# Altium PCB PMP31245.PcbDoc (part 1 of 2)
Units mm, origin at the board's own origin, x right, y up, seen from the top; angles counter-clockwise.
Board outline 106.43 x 50.29 mm, 4 copper layers (Top Layer, GND, Layer 2, Bottom Layer), stack 0.603 mm thick; 132 components, 64 nets, 341 pads, 146 vias.
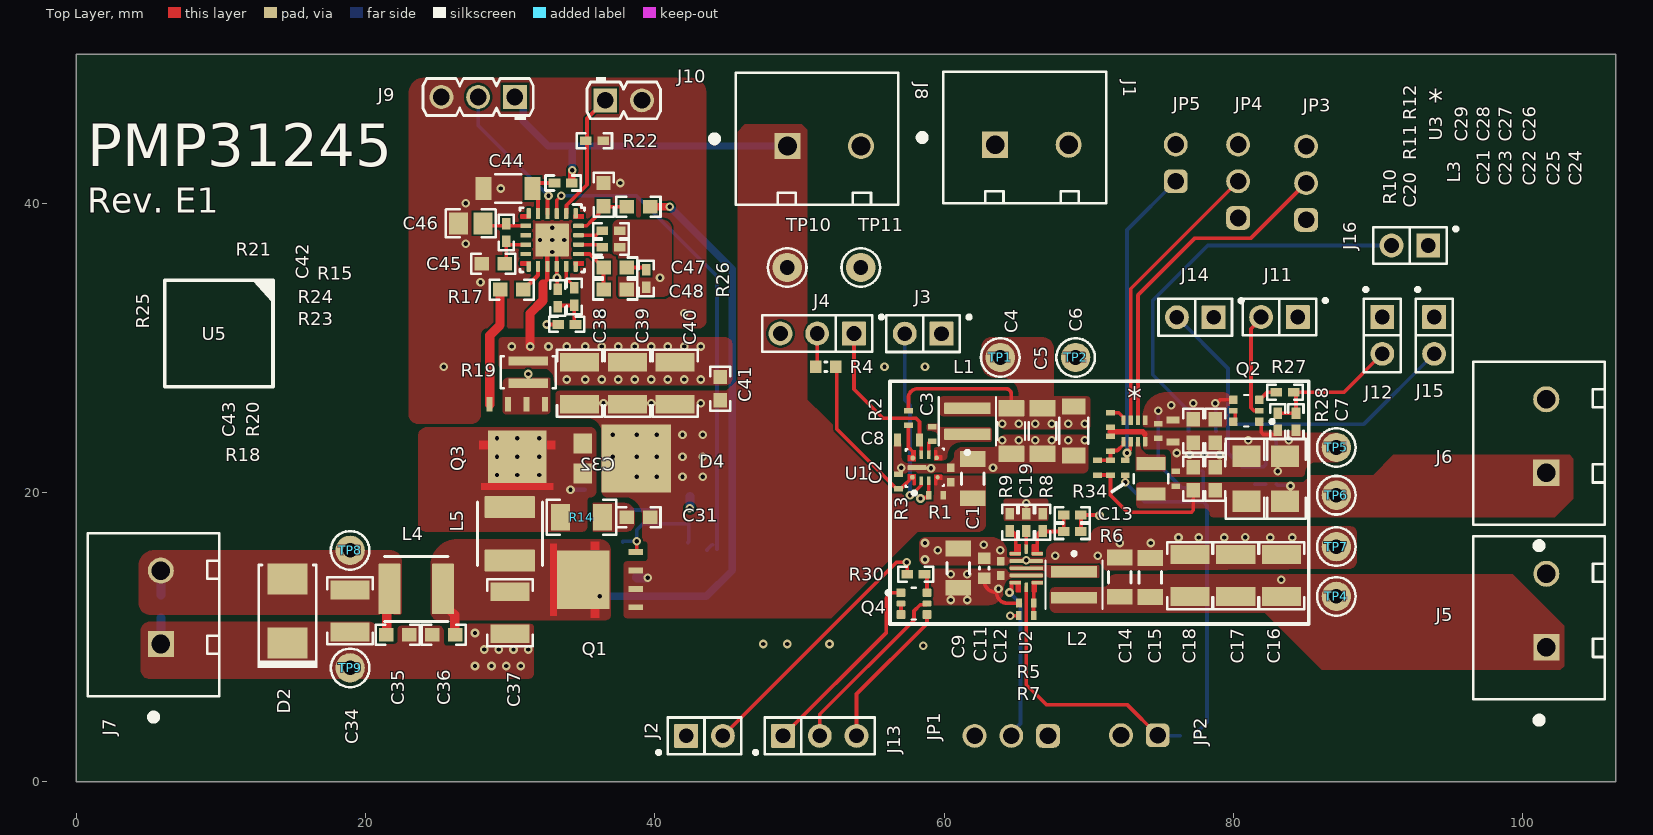
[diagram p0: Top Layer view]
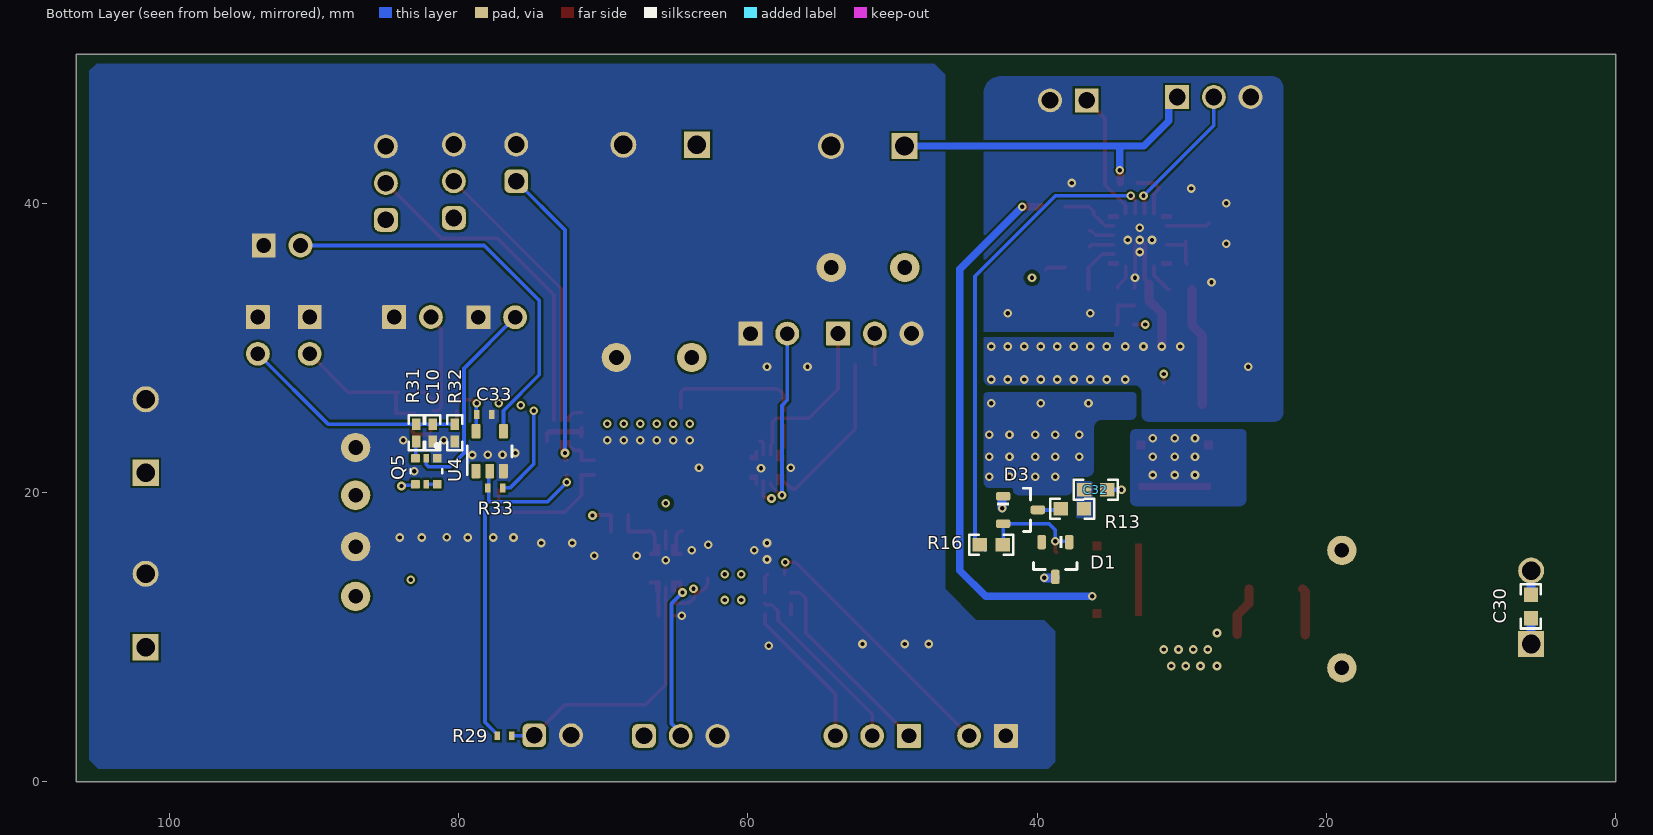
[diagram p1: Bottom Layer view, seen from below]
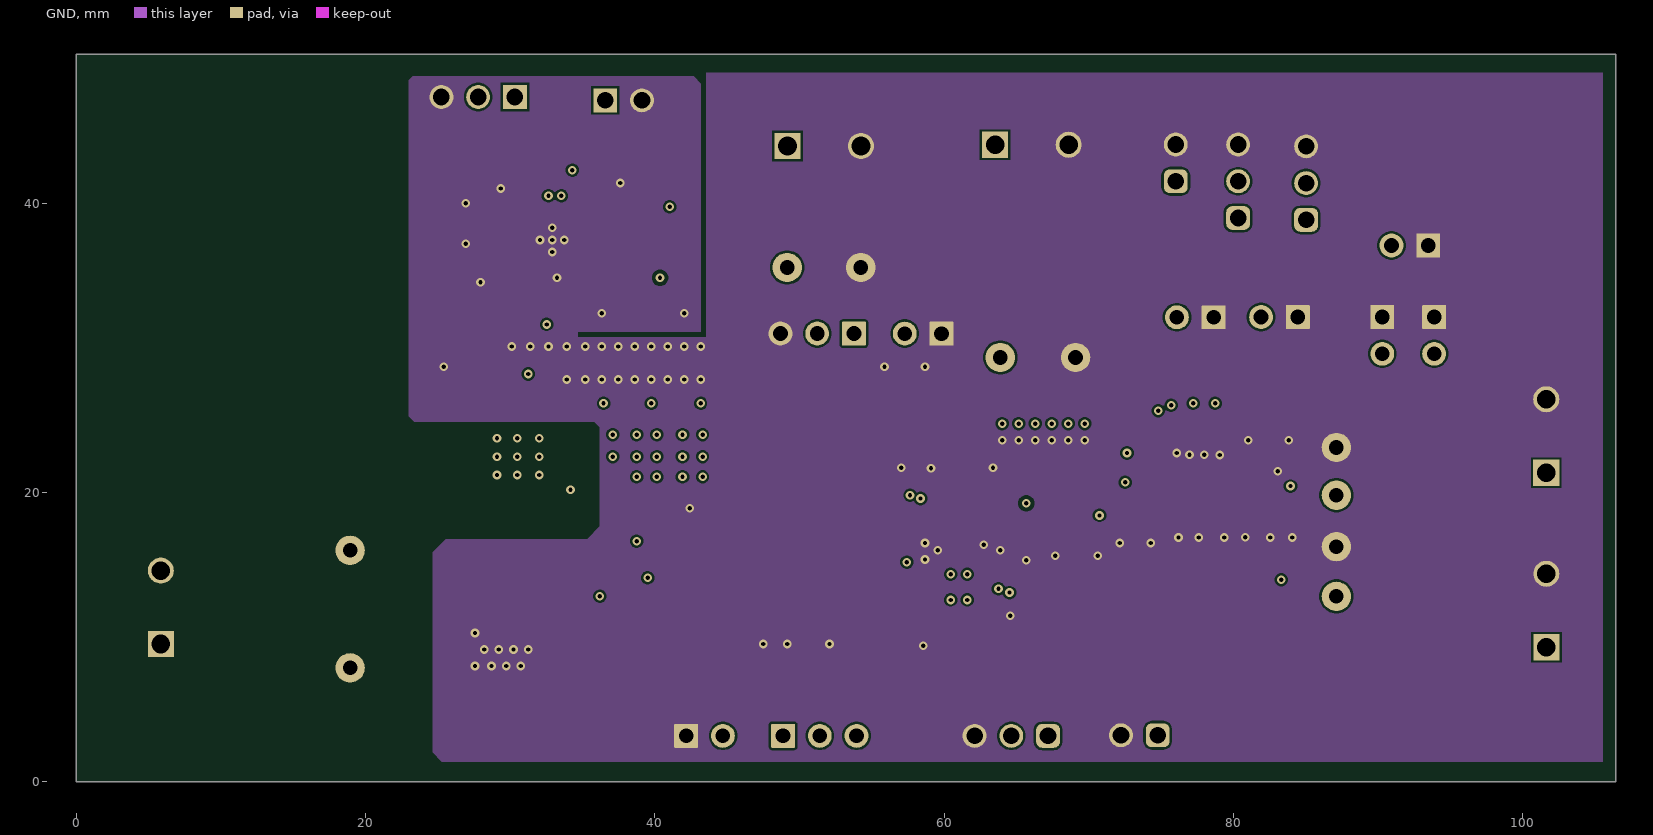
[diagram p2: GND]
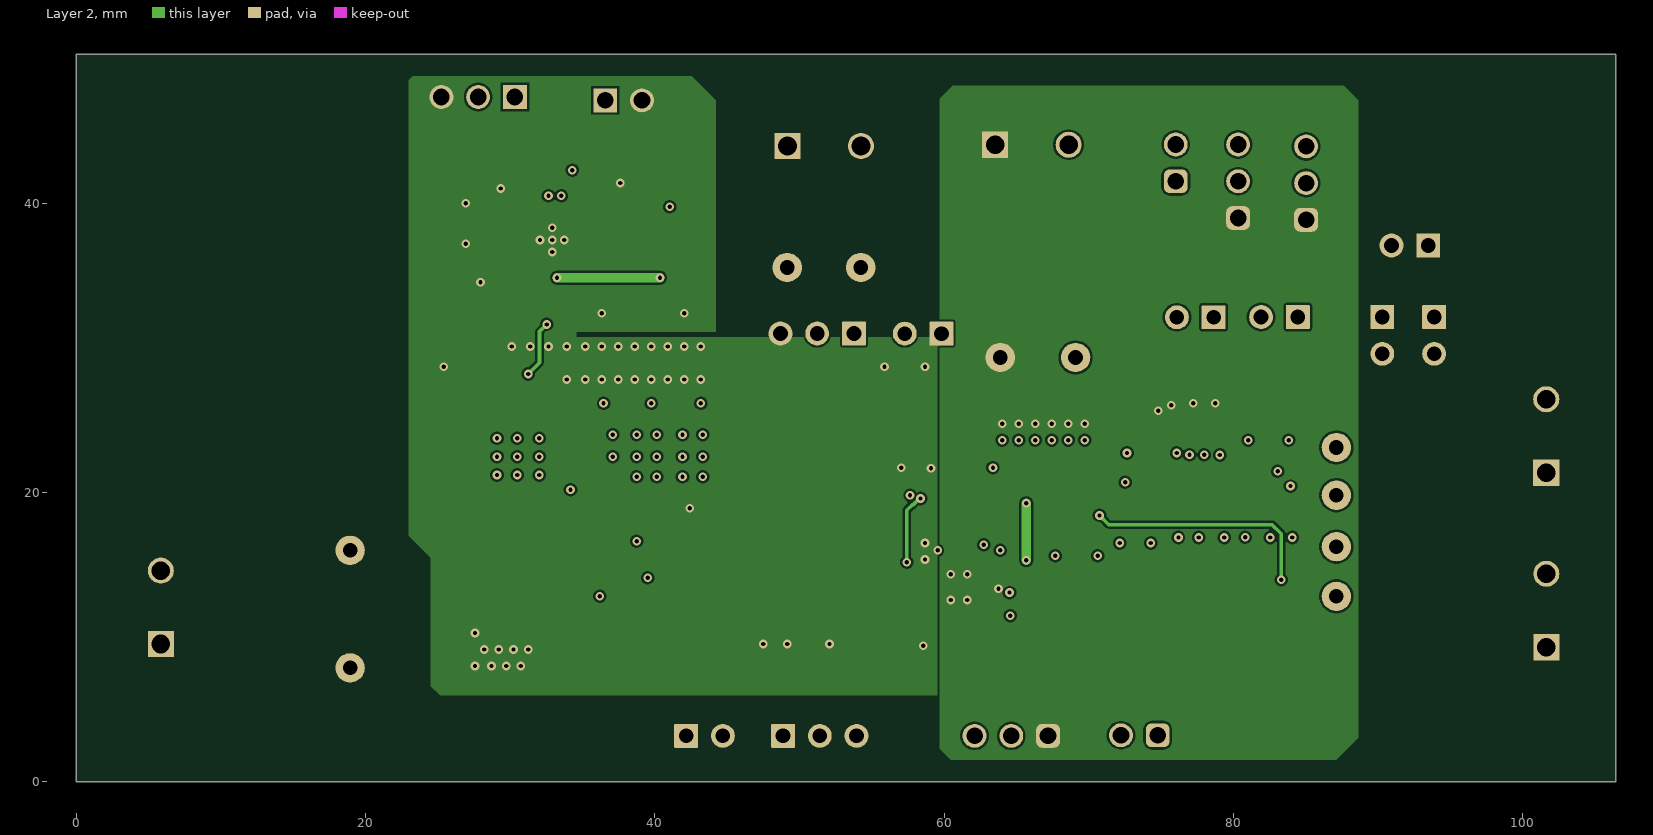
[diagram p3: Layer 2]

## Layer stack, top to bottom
Top Solder: solder mask 0.0102, Solder Resist, Dk 3.5
Top Layer: signal copper 0.0356
Dielectric 2: prepreg 0.0711, PP-006, Dk 4.1
GND: signal copper 0.035
Dielectric 1: dielectric 0.32, FR-4, Dk 4.8
Layer 2: signal copper 0.035
Dielectric 3: prepreg 0.0711, PP-006, Dk 4.1
Bottom Layer: signal copper 0.0356
Bottom Solder: solder mask 0.0102, Solder Resist, Dk 3.5

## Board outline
0,0 0,50.292 106.426,50.292 106.426,0

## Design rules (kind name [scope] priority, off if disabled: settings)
Clearance [All] p1: gap=0.152 ignorepadtopadclearanceinfootprint=FALSE except(0: Arc-Hole Track-Hole SMDPad-Hole THPad-Hole Via-Hole Fill-Hole Poly-Hole Region-Hole Text-Hole)
HoleSize [All] p1: absolutevalues=TRUE maxlimit=2.54 minlimit=0.3 maxpercent=80.000 minpercent=20.000
MinimumAnnularRing [All] p1: minimumring=0.2
PolygonConnect [All] p1: connectstyle=Direct reliefconductorwidth=0.254 reliefentries=4 polygonreliefangle="90 Angle" airgapwidth=0.254
RoutingVias [All] p1: holewidth=0.3 width=0.6 viastyle="Through Hole" minholewidth=0.3 minwidth=0.6 maxholewidth=0.711 maxwidth=1.27
SolderMaskExpansion [All] p1: expansion=0.102 istentingtop=FALSE
Width [All] p1: maxlimit=1.27 minlimit=0.254 preferedwidth=0.254 minimp=50.000000 maximp=50.000000 favimp=50.000000
29 further rules are at their usual default settings.

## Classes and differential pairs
component class PMP31245_Boost: C30 C31 C32 C34 C35 C36 C37 C38 C39 C40 C41 C42 C43 C44 C45 C46 C47 C48 D1 D2 D3 D4 J7 J8 J9 J10 L4 L5 Q1 Q3 R13 R14 R15 R16 R17 R18 R19 R20 R21 R22 R23 R24 R25 R26 TP8 TP9 TP10 TP11 U5
component class PMP31245_Buck: C1 C2 C3 C4 C5 C6 C7 C8 C9 C10 C11 C12 C13 C14 C15 C16 C17 C18 C19 C20 C21 C22 C23 C24 C25 C26 C27 C28 C29 C33 J1 J2 J3 J4 J5 J6 J11 J12 J13 J14 J15 J16 JP1 JP2 JP3 JP4 JP5 L1 L2 L3 Q2 Q4 Q5 R1 R2 R3 R4 R5 R6 R7 R8 R9 R10 R11 R12 R27 R28 R29 R30 R31 R32 R33 R34 TP1 TP2 TP4 TP5 TP6 TP7 U1 U2 U3 U4

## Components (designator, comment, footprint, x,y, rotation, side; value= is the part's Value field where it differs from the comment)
C1 "CIN" 1206_180L 61.976,20.955 r270 top value=4.7uF
C2 "CINHF" 0402L 60.452,21.209 r90 top value=0.1uF
C3 "CB" 0402S 59.178,24.051 r90 top value=0.1uF
C4 "COUT1" FP-GRM31CC81E226KE11L_1206-MFG 64.643,24.257 r90 top value=22µF
C5 "COUT2" FP-GRM31CC81E226KE11L_1206-MFG 66.802,24.257 r90 top value=22µF
C6 "COUT3" 1206_190 68.961,24.257 r90 top value=10uF
C7 "CGA2B2X7R1H222K050BA" 0402 84.328,24.892 r270 top value=2200pF
C8 "CVCC" 0603S 57.531,23.622 r180 top value=1uF
C9 "GCM31CR71A226KE02" 1206_180L 60.985,14.765 r90 top value=22uF
C10 "CGA2B2X7R1H222K050BA" 0402 81.788,24.13 r270 bottom value=2200pF
C11 "GCM188C71A225K" 0603L 62.763,14.765 r90 top value=2.2uF
C12 "GCM155R71H471KA37D" 0402L 63.906,14.757 r90 top value=470pF
C13 "GCM1555C1H220JA16D" 0402 68.859,18.448 r180 top value=22pF
C14 "GCM31CR71A226KE02" 1206_180L 72.136,14.144 r90 top value=22uF
C15 "GCM31CR71A226KE02" 1206_180L 74.261,14.128 r90 top value=22uF
C16 "GRM32ER60J107ME20L" 1210_270 83.337,14.257 r90 top value=100uF
C17 "GRM32ER60J107ME20L" 1210_270 80.162,14.257 r90 top value=100uF
C18 "GRM32ER60J107ME20L" 1210_270 76.987,14.257 r90 top value=100uF
C19 "GCM155R71H472KA37D" 0402 65.684,17.94 r90 top value=4700pF
C20 "GCM1555C1H100JA16D" 0402S 71.501,21.717 r90 top value=10pF
C21 "C0402C104K4RACAUTO" 0402S 76.015,20.952 r90 top value=0.1uF
C22 "GRM188Z71A106MA73D" 0603 78.74,20.955 r90 top value=10uF
C23 "GRM188Z71A106MA73D" 0603 77.216,20.955 r90 top value=10uF
C24 "GCM31CR71A226KE02" 1206_180M 83.566,20.955 r90 top value=22uF
C25 "GCM31CR71A226KE02" 1206_180M 80.899,20.955 r90 top value=22uF
C26 "GRM188Z71A106MA73D" 0603 78.74,24.257 r270 top value=10uF
C27 "GRM188Z71A106MA73D" 0603 77.216,24.257 r270 top value=10uF
C28 "GRM188R71C474KA88D" 0603S 75.819,24.257 r270 top value=0.47uF
C29 "CGA2B2X7R1H471K050BA" 0402S 74.803,24.257 r90 top value=470pF
C30 "GRM188R71H104KA93D" 0603 5.851,12.12 r90 bottom value=0.1uF
C31 "GRM188R71H271KA01D" 0603 38.862,18.288 r180 top value=270pF
C32 "GRM188R72A103KA01D" 0603 35.941,20.193 r180 bottom value=0.01uF
C33 "C0402C104K4RACAUTO" 0402S 78.232,25.4 r180 bottom value=0.1uF
C34 "GRM32ER71H106KA12L" 1210_270 18.923,11.811 r270 top value=10uF
C35 "GRM188R71H104KA93D" 0603 22.225,10.16 r180 top value=0.1uF
C36 "GRM188R71H104KA93D" 0603 25.4,10.16 r0 top value=0.1uF
C37 "GRM32ER71H106KA12L" 1210_270 29.972,11.684 r270 top value=10uF
C38 "GRM32ER71H106KA12L" 1210_270 34.798,27.559 r90 top value=10uF
C39 "GRM32ER71H106KA12L" 1210_270 38.1,27.559 r90 top value=10uF
C40 "GRM32ER71H106KA12L" 1210_270 41.402,27.559 r90 top value=10uF
C41 "GRM188R71H104KA93D" 0603 44.513,27.187 r90 top value=0.1uF
C42 "GRM188R71H104KA93D" 0603 36.449,40.602 r270 top value=0.1uF
C43 "CGA2B2X7R1H222K050BA" 0402 33.277,33.445 r270 top value=2200pF
C44 "GRM31CR71H225KA88L" 1206_180 29.845,41.021 r180 top value=2.2uF
C45 "GRM188R71H104KA93D" 0603 28.829,35.814 r180 top value=0.1uF
C46 "GRM21BR71C475KA73L" 0805 27.266,38.608 r0 top value=4.7uF
C47 "GRM188R71E474KA12D" 0603 37.249,35.56 r0 top value=0.47uF
C48 "GRM188R71H683KA93D" 0603 37.249,34.036 r0 top value=0.068uF
D1 "BZX84C16LT1G" SOT-23 38.735,15.367 r270 bottom value=16V
D2 "SMBJ36CA" SMB 14.597,11.811 r90 top value=36V
D3 "BAV99" SOT-23 41.148,18.796 r180 bottom value=75V
D4 "SS5P6" TO-277A 36.83,22.352 r90 top value=60V
J1 "OSTTA024163" On-Shore_OSTTA024163 65.569,44.546 r0 top
J2 "JEN" Samtec_HTSW-102-07-G-S 43.43,3.175 r0 top
J3 "JEN" Samtec_HTSW-102-07-G-S 58.547,30.988 r180 top
J4 "JMODE/SYNC" Samtec_HTSW-103-07-G-S 51.221,30.992 r180 top
J5 "OSTTA024163" On-Shore_OSTTA024163 101.139,11.342 r90 top
J6 "OSTTA024163" On-Shore_OSTTA024163 101.133,23.407 r90 top
J7 "OSTTA024163" On-Shore_OSTTA024163 5.334,11.557 r90 top
J8 "OSTTA024163" On-Shore_OSTTA024163 51.205,44.461 r0 top
J9 "61300311121" WURTH_61300311121#1 27.779,47.347 r180 top
J10 "61300211121" WURTH_61300211121#1 37.834,47.118 r0 top
J11 "JEN" Samtec_HTSW-102-07-G-S 83.185,32.131 r180 top
J12 "JEN" Samtec_HTSW-102-07-G-S 90.297,30.861 r270 top
J13 "JMODE/SYNC" Samtec_HTSW-103-07-G-S 51.402,3.175 r0 top
J14 "JEN" Samtec_HTSW-102-07-G-S 77.363,32.118 r180 top
J15 "JEN" Samtec_HTSW-102-07-G-S 93.884,30.861 r270 top
J16 "JEN" Samtec_HTSW-102-07-G-S 92.202,37.084 r180 top
JP1 "61300311121" WURTH_61300311121#2 64.643,3.175 r180 top
JP2 "61300211121" WURTH_61300211121#2 73.496,3.214 r180 top
JP3 "61300311121" WURTH_61300311121#2 85.027,41.395 r90 top
JP4 "61300311121" WURTH_61300311121#2 80.328,41.522 r90 top
JP5 "61300211121" WURTH_61300211121#2 76.015,42.792 r90 top
L1 "XGL3530-222MEC" FP-XGL3530-222MEC_SMT_IND_3MM2_3MM5-MFG 61.604,24.925 r90 top value=2.2uH
L2 "XGL3530-601MEC" FP-XGL3530_SMT_IND_3MM2_3MM5-MFG 68.986,13.622 r270 top value=3.3uH
L3 "DFE252012PD-R47M" DFE252012P 74.295,20.955 r270 top value=470nH
L4 "VCHA054T-3R3MS6" VCHA042A 23.495,13.335 r0 top value=3.3uH
L5 "VCHA054T-3R3MS6" VCHA042A 29.972,17.145 r90 top value=3.3uH
Q1 "SQJ459EP" PowerPAK_SO-8L 35.857,13.97 r180 top value=-60V
Q2 "PUMD13,115" FP-PUMD13,115_TSSOP6-MFG 80.899,25.654 r180 top value=50V
Q3 "BUK9Y12-40" PowerPAK_SO-8L 30.48,23.284 r270 top value=60V
Q4 "PUMD13,115" FP-PUMD13,115_TSSOP6-MFG 57.912,12.319 r0 top value=50V
Q5 "PUMD13,115" FP-PUMD13,115_TSSOP6-MFG 82.236,21.464 r270 bottom value=50V
R1 "RENT" 0402S 59.436,19.812 r0 top value=100k
R2 "RINJ" 0402S 57.531,25.146 r270 top value=0
R3 "RT" 0402S 56.838,20.755 r90 top value=6.49k
R4 "RJM" 0603L 51.816,28.702 r0 top value=0
R5 "RINJ" 0402S 65.684,12.352 r0 top value=0
R6 "CRCW040220K0FKED" 0402 68.859,17.305 r0 top value=20.0k
R7 "DNP" 0402S 65.673,11.487 r180 top value=0
R8 "CRCW040232K4FKED" 0402 66.827,17.94 r270 top value=32.4k
R9 "CRCW04028K06FKED" 0402 64.541,17.94 r270 top value=8.06k
R10 "CRCW040280K6FKED" 0402S 70.612,21.717 r270 top value=80.6k
R11 "CRCW040240K2FKED" 0402S 71.501,23.368 r270 top value=40.2k
R12 "CRCW04028K06FKED" 0402S 71.501,25.019 r90 top value=8.06k
R13 "CRCW060310R0FKEA" 0603 37.557,18.869 r0 bottom value=10.0
R14 "CRCW12068R20JNEA" 1206 34.925,18.288 r0 top value=8.2
R15 "CRCW06033R32FKEA" 0603 38.862,39.751 r180 top value=3.32
R16 "CRCW060349K9FKEA" 0603 43.18,16.383 r0 bottom value=49.9k
R17 "CRCW06034R75FKEA" 0603 30.099,34.036 r180 top value=4.75
R18 "RMCF0402JT100R" 0402 33.909,31.623 r180 top value=100
R19 "PRL1632-R008-F-T1" 0612 31.242,28.321 r270 top value=0.008
R20 "ERJ-2GE0R00X" 0402 34.419,33.557 r270 top value=0
R21 "ERJ-2GE0R00X" 0402 33.655,41.402 r0 top value=0
R22 "ERJ-2GE0R00X" 0402 35.814,44.323 r180 top value=0
R23 "CRCW040253K6FKED" 0402 36.957,36.957 r180 top value=53.6k
R24 "CRCW04029K53FKED" 0402 36.957,38.1 r180 top value=9.53k
R25 "CRCW040210R0JNED" 0402 29.718,37.973 r90 top value=10
R26 "CRCW0402200RFKED" 0402 39.408,34.798 r90 top value=200
R27 "AC0402FR-0710KL" 0402 83.566,26.924 r0 top value=10.0k
R28 "AC0402FR-0710KL" 0402 83.058,24.892 r90 top value=10.0k
R29 "RINJ" 0402S 76.835,3.175 r0 bottom value=0
R30 "CRCW040247R0JNED" 0402 58.039,14.351 r180 top value=47
R31 "AC0402FR-0710KL" 0402 82.931,24.13 r90 bottom value=10.0k
R32 "AC0402FR-0710KL" 0402 80.264,24.13 r90 bottom value=10.0k
R33 "RENT" 0402S 77.47,20.32 r180 bottom value=100k
R34 "RINJ" 0402S 72.517,21.717 r270 top value=0
TP1 "5000" Keystone5000 63.881,29.337 r0 top
TP2 "5001" Keystone5001 69.088,29.337 r90 top
TP4 "5000" Keystone5000 87.122,12.818 r90 top
TP5 "5001" Keystone5001 87.122,23.114 r90 top
TP6 "5000" Keystone5000 87.122,19.812 r90 top
TP7 "5001" Keystone5001 87.122,16.256 r90 top
TP8 "5000" Keystone5000 18.923,16.002 r90 top
TP9 "5001" Keystone5001 18.923,7.874 r90 top
TP10 "5000" Keystone5000 49.146,35.56 r90 top
TP11 "5001" Keystone5001 54.234,35.56 r90 top
U1 "LMR43620MSC5RPERQ1" RPE0009A-MFG 58.674,21.717 r90 top
U2 "TPS62810QWRWYRQ1" RWY0009A 65.684,14.765 r180 top
U3 "TPS62850QDRLRQ1" DRL0008A 73.152,24.257 r270 top
U4 "SN74AUC1G07DBVR" DBV0005A_N 77.851,22.86 r90 bottom
U5 "LM5150-Q1" RUM0016C 32.893,37.465 r270 top

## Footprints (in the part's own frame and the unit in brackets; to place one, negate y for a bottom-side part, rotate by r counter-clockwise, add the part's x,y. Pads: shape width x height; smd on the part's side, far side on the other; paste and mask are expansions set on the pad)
0402 [mm] "0402 from SM-752 data"
  rect 0.8x0.6 smd: 1(-0.6,0) 2(0.6,0)
  silkscreen extent -1.22,-0.52 1.22,0.52, body extent -0.55,-0.3 0.55,0.3, height 0.6
0402L [mm] "0402 from SM-752 data"
  rect 0.6x0.5 smd: 1(-0.5,0) 2(0.5,0)
  body extent -0.55,-0.3 0.55,0.3, height 0.6
0402S [mil] "Based on C0402S footprint from PADS legacy"
  rect 15x24 smd: 1(-20,0) 2(20,0)
  body extent -22,-12 22,12, height 24
0603 [mm] "0603 from SM-752 data"
  rect 1x0.95 smd: 1(-0.8,0) 2(0.8,0)
  silkscreen extent -1.52,-0.69 1.52,0.69, body extent -0.87,-0.47 0.87,0.47, height 1
0603L [mm] "0603 from SM-752 data"
  rect 0.8x0.85 smd: 1(-0.7,0) 2(0.7,0)
  silkscreen extent -0.07,-0.33 0.07,0.33, body extent -0.87,-0.47 0.87,0.47, height 1
0603S [mil]
  rect 20x35 smd: 1(-30,0) 2(30,0)
  body extent -34,-19 34,19, height 39
0612 [mm] "Panasonic recommended land pattern, fb97d03ed01.pdf dated April 2008"
  rect 0.65x2.75 smd: 1(-0.775,0) 2(0.775,0)
  silkscreen extent -1.1,-1.9 1.1,1.9, body extent -0.9,-1.7 0.9,1.7, height 0.85
0805 [mm] "0805 from SM-752 data"
  rect 1.3x1.5 smd: 1(-0.85,0) 2(0.85,0)
  silkscreen extent -1.72,-0.97 1.72,0.97, body extent -1.1,-0.72 1.1,0.72, height 1.45
1206 [mm] "1206 from SM-752 data"
  rect 1.3x1.85 smd: 1(-1.45,0) 2(1.45,0)
  silkscreen extent -2.4,-1.21 2.4,1.21, body extent -1.7,-0.9 1.7,0.9, height 1.35
1206_180 [mm] "1206_180"
  rect 1.1x1.6 smd: 1(-1.7,0) 2(1.7,0)
  silkscreen extent -0.9,-1 0.9,1, body extent -1.75,-0.95 1.75,0.95, height 1.8
1206_180L [mm] "1206_180"
  rect 1.1x1.75 smd: 1(-1.35,0) 2(1.35,0)
  silkscreen extent -0.4,-0.77 0.4,0.77, body extent -1.75,-0.95 1.75,0.95, height 1.8
1206_180M [mm] "1206_180"
  rect 1.5x1.95 smd: 1(-1.55,0) 2(1.55,0)
  silkscreen extent -2.76,-1.44 2.76,1.44, body extent -1.75,-0.95 1.75,0.95, height 1.8
1206_190 [mm] "1206_190"
  rect 1.1x1.6 smd: 1(-1.7,0) 2(1.7,0)
  silkscreen extent -0.9,-1 0.9,1, body extent -1.75,-0.95 1.75,0.95, height 1.9
1210_270 [mm] "1210"
  rect 1.3x2.7 smd: 1(-1.45,0) 2(1.45,0)
  silkscreen extent -2.32,-1.57 2.32,1.57, body extent -1.7,-1.35 1.7,1.35, height 2.7
DBV0005A_N [mm] "SOT23, 5-Leads, Body 2.9x1.6mm, Pitch 0.95mm, Lead Span 2.8mm, IPC Medium Density"
  rrect17% 1x0.6 smd: 1(-1.375,0.95) 2(-1.375,0) 3(-1.375,-0.95) 4(1.375,-0.95) 5(1.375,0.95)
  silkscreen extent -1.63,-1.55 0.38,1.55, body extent -1.42,-1.46 1.42,1.46, height 1.09
DFE252012P [mm] "TOKO, Pad sizes increased as per request"
  rect 0.9x2 smd: 1(-1.05,0) 2(1.05,0)
  silkscreen extent -0.3,-1.2 0.3,1.2, body extent -1.35,-1.1 1.35,1.1, height 1.2
DRL0008A [mm] "SOT-5X3-8"
  rrect33% 0.67x0.3 smd: 1(-0.74,0.75) 2(-0.74,0.25) 3(-0.74,-0.25) 4(-0.74,-0.75) 5(0.74,-0.75) 6(0.74,-0.25) 7(0.74,0.25) 8(0.74,0.75)
  body extent -0.8,-1.05 0.8,1.05, height 0.61
FP-GRM31CC81E226KE11L_1206-MFG [mm]
  rrect9% 1.15x1.8 smd paste+0 mask+0: 1(-1.575,0) 2(1.575,0)
  silkscreen extent -0.63,-0.95 0.63,0.95, body extent -2.25,-1.05 2.25,1.05, height 0.25
FP-PUMD13,115_TSSOP6-MFG [mm]
  rrect17% 0.6x0.6 smd paste-1000 mask+0: 1(-0.9,0.75) 3(-0.9,-0.75) 4(0.9,-0.75) 6(0.9,0.75)
  rrect25% 0.6x0.4 smd paste+0 mask+0: 2(-0.9,0) 5(0.9,0)
  silkscreen extent -1.9,-1.1 0.15,1.1, body extent -1.33,-1.2 1.33,1.2, height 0.25
FP-XGL3530-222MEC_SMT_IND_3MM2_3MM5-MFG [mm]
  rrect12% 0.81x3.2 smd paste+0 mask+0: 1(-0.9,0) 2(0.9,0)
  silkscreen extent -2.27,-1.97 1.68,1.97, body extent -1.78,-1.92 1.78,1.92, height 0.25
FP-XGL3530_SMT_IND_3MM2_3MM5-MFG [mm]
  rrect12% 0.81x3.2 smd paste+0 mask+0: 1(-0.9,0) 2(0.9,0)
  silkscreen extent -2.27,-1.97 1.68,1.97, body extent -1.78,-1.92 1.78,1.92, height 0.25
Keystone5000 [mil] "For Keystone 500x miniature loop terminals"
  round 80 hole 40: 1(0,0)
  silkscreen extent -52,-52 52,52, body extent -49,-49 49,49, height 182
Keystone5001 [mil] "For Keystone 500x miniature loop terminals"
  round 80 hole 40: 1(0,0)
  silkscreen extent -52,-52 52,52, body extent -49,-49 49,49, height 182
On-Shore_OSTTA024163 [mm] "TERM BLOCK 2x1, 5.08mm, TH"
  rect 1.8x1.8 hole 1.3: 1(-2.04,-0.5)
  round 1.8 hole 1.3 paste+0: 2(3.04,-0.5)
  silkscreen extent -7.18,-4.55 5.63,4.55, body extent -5.68,-4.6 5.68,4.6, height 13
PowerPAK_SO-8L [mm] "based on Vishay recommended land pattern Document 63818 Feb 7, 2012"
  rect 1x0.41 smd: 1(-2.805,1.905) 2(-2.805,0.635) 3(-2.805,-0.635) 4(-2.805,-1.905)
  rect 3.63x4.061 smd: 5(0.805,0)
  Top Layer region: -0.298,-2.64 0.297,-2.64 0.297,-2.03 -0.298,-2.03
  Top Layer region: -0.297,2.03 0.298,2.03 0.298,2.64 -0.297,2.64
  Top Layer region: 2.615,-2.5 3.125,-2.5 3.125,2.5 2.615,2.5
  body extent -3.07,-2.57 3.08,2.57, height 1.21
RPE0009A-MFG [mm]
  round 0.342 smd paste-1000 mask+0: 1(-0.661,0.877)
  rrect40% 0.6x0.25 smd paste+0 mask+0: 2(-0.9,0.25) 3(-0.9,-0.25) 6(0.9,-0.25) 7(0.9,0.25)
  round 0.291 smd paste+0 mask+0: 4(-0.661,-0.877)
  round 0.323 smd paste+0 mask+0: 5(0.68,-0.805)
  round 0.346 smd paste-1000 mask+0: 8(0.665,0.841)
  rrect29% 0.35x1.3 smd paste-1000 mask+0: 9(0,0.55)
  Top Layer region: 1.2,0.8 1.193,0.825 1.175,0.844 1.15,0.85 1.15,0.85 0.9,0.851 0.881,0.854 0.865,0.865 0.854,0.881 0.85,0.901 0.85,0.901 0.85,1.15 0.843,1.175 0.825,1.193 0.8,1.2 0.8,1.2 0.5,1.2 0.481,1.196 0.465,1.185 0.454,1.169 0.45,1.15 0.45,1.15 0.45,0.676 0.454,0.656 0.465,0.64 0.481,0.629 0.5,0.626 0.5,0.625 1.15,0.626 1.169,0.629 1.185,0.64 1.196,0.656 1.2,0.676 1.2,0.676
  Top Layer region: 1.2,-0.8 1.193,-0.825 1.175,-0.844 1.15,-0.85 1.15,-0.851 0.9,-0.85 0.881,-0.854 0.865,-0.865 0.854,-0.881 0.85,-0.9 0.85,-0.901 0.85,-1.15 0.843,-1.175 0.825,-1.193 0.8,-1.2 0.8,-1.2 0.55,-1.2 0.531,-1.196 0.515,-1.185 0.504,-1.169 0.5,-1.15 0.5,-1.15 0.5,-0.676 0.504,-0.656 0.515,-0.64 0.531,-0.629 0.55,-0.625 0.55,-0.625 1.15,-0.626 1.169,-0.629 1.185,-0.64 1.196,-0.656 1.2,-0.676 1.2,-0.676
  Top Layer region: -1.2,-0.8 -1.193,-0.825 -1.175,-0.844 -1.15,-0.85 -1.15,-0.85 -0.9,-0.851 -0.881,-0.854 -0.865,-0.865 -0.854,-0.881 -0.85,-0.901 -0.85,-0.901 -0.85,-1.15 -0.843,-1.175 -0.825,-1.193 -0.8,-1.2 -0.8,-1.2 -0.55,-1.2 -0.531,-1.196 -0.515,-1.185 -0.504,-1.169 -0.5,-1.15 -0.5,-1.15 -0.5,-0.676 -0.504,-0.656 -0.515,-0.64 -0.531,-0.629 -0.55,-0.626 -0.55,-0.625 -1.15,-0.626 -1.169,-0.629 -1.185,-0.64 -1.196,-0.656 -1.2,-0.676 -1.2,-0.676
  Top Layer region: -1.2,0.8 -1.193,0.825 -1.175,0.844 -1.15,0.85 -1.15,0.851 -0.9,0.851 -0.881,0.854 -0.865,0.865 -0.854,0.881 -0.85,0.901 -0.85,0.901 -0.85,1.15 -0.843,1.175 -0.825,1.193 -0.8,1.2 -0.8,1.2 -0.5,1.2 -0.481,1.196 -0.465,1.185 -0.454,1.169 -0.45,1.15 -0.45,1.15 -0.45,0.676 -0.454,0.656 -0.465,0.64 -0.481,0.629 -0.5,0.626 -0.5,0.625 -1.15,0.626 -1.169,0.629 -1.185,0.64 -1.196,0.656 -1.2,0.676 -1.2,0.676
  silkscreen extent -1.87,-1.33 1.33,1.33, body extent -1.3,-1.3 1.3,1.3, height 0.25
RUM0016C [mm] "QFN, 16-Leads, Body 4x4mm, Pitch 0.65mm, Thermal Pad 2.3x2.3mm, TI Recommended"
  rrect33% 0.75x0.3 smd: 1(-1.825,0.975) 2(-1.825,0.325) 3(-1.825,-0.325) 4(-1.825,-0.975) 9(1.825,-0.975) 10(1.825,-0.325) 11(1.825,0.325) 12(1.825,0.975)
  rrect33% 0.3x0.75 smd: 5(-0.975,-1.825) 6(-0.325,-1.825) 7(0.325,-1.825) 8(0.975,-1.825) 13(0.975,1.825) 14(0.325,1.825) 15(-0.325,1.825) 16(-0.975,1.825)
  rrect10% 1.02x1.02 on Top Paste: 17(-0.61,0.61) 17(-0.61,-0.61) 17(0.61,0.61) 17(0.61,-0.61)
  rrect4% 2.3x2.3 smd paste-1.35: 17(0,0)
  rrect36% 0.725x0.275 on Top Paste: A1(-1.837,1.613) A2(-1.837,-1.613) A3(1.837,-1.613) A4(1.837,1.613)
  rrect33% 0.725x0.3 smd paste-0.15: A1(-1.837,1.625) A2(-1.837,-1.625) A3(1.837,-1.625) A4(1.837,1.625)
  rrect36% 0.275x0.725 on Top Paste: A1(-1.613,1.837) A2(-1.613,-1.837) A3(1.613,-1.837) A4(1.613,1.837)
  Top Layer region: 1.775,1.525 1.775,2.15 1.771,2.169 1.76,2.185 1.744,2.196 1.725,2.2 1.725,2.2 1.525,2.2 1.506,2.196 1.49,2.185 1.479,2.169 1.475,2.15 1.475,2.15 1.475,1.525 1.479,1.506 1.49,1.49 1.506,1.479 1.525,1.475 1.525,1.475 1.725,1.475 1.744,1.479 1.76,1.49 1.771,1.506 1.775,1.525
  Top Layer region: 1.775,-1.525 1.775,-2.15 1.771,-2.169 1.76,-2.185 1.744,-2.196 1.725,-2.2 1.725,-2.2 1.525,-2.2 1.506,-2.196 1.49,-2.185 1.479,-2.169 1.475,-2.15 1.475,-2.15 1.475,-1.525 1.479,-1.506 1.49,-1.49 1.506,-1.479 1.525,-1.475 1.525,-1.475 1.725,-1.475 1.744,-1.479 1.76,-1.49 1.771,-1.506 1.775,-1.525
  Top Layer region: -1.775,-1.525 -1.775,-2.15 -1.771,-2.169 -1.76,-2.185 -1.744,-2.196 -1.725,-2.2 -1.725,-2.2 -1.525,-2.2 -1.506,-2.196 -1.49,-2.185 -1.479,-2.169 -1.475,-2.15 -1.475,-2.15 -1.475,-1.525 -1.479,-1.506 -1.49,-1.49 -1.506,-1.479 -1.525,-1.475 -1.525,-1.475 -1.725,-1.475 -1.744,-1.479 -1.76,-1.49 -1.771,-1.506 -1.775,-1.525
  Top Layer region: -1.775,1.525 -1.775,2.15 -1.771,2.169 -1.76,2.185 -1.744,2.196 -1.725,2.2 -1.725,2.2 -1.525,2.2 -1.506,2.196 -1.49,2.185 -1.479,2.169 -1.475,2.15 -1.475,2.15 -1.475,1.525 -1.479,1.506 -1.49,1.49 -1.506,1.479 -1.525,1.475 -1.525,1.475 -1.725,1.475 -1.744,1.479 -1.76,1.49 -1.771,1.506 -1.775,1.525
  silkscreen extent -2.45,-2.23 2.23,2.22, body extent -2,-2 2,2, height 0.8
RWY0009A [mm] "VQFN-HR-9"
  rrect40% 0.775x0.25 smd paste-0.2: 1(-0.761,1) 5(-0.761,-1) 7(0.761,-1) 8(0.761,1)
  rrect40% 1.05x0.25 on Top Paste: 2(-0.625,0.5) 2(0.625,0.5) 3(-0.625,0) 3(0.625,0) 4(-0.625,-0.5) 4(0.625,-0.5)
  rrect40% 2.3x0.25 smd paste-0.5: 2(0,0.5) 3(0,0) 4(0,-0.5)
  rrect40% 0.25x0.65 smd: 6(0,-1.325) 9(0,1.325)
  Top Layer region: -1.1,-1.125 -1.119,-1.121 -1.135,-1.11 -1.146,-1.094 -1.15,-1.075 -1.15,-1.075 -1.15,-0.925 -1.146,-0.906 -1.135,-0.89 -1.119,-0.879 -1.1,-0.875 -1.1,-0.875 -0.425,-0.875 -0.406,-0.879 -0.39,-0.89 -0.379,-0.906 -0.375,-0.925 -0.375,-0.925 -0.375,-1.6 -0.379,-1.619 -0.39,-1.635 -0.406,-1.646 -0.425,-1.65 -0.425,-1.65 -0.675,-1.65 -0.694,-1.646 -0.71,-1.635 -0.721,-1.619 -0.725,-1.6 -0.725,-1.6 -0.725,-1.175 -0.729,-1.156 -0.74,-1.14 -0.756,-1.129 -0.775,-1.125 -0.775,-1.125
  Top Layer region: 0.375,-1.6 0.379,-1.619 0.39,-1.635 0.406,-1.646 0.425,-1.65 0.425,-1.65 0.675,-1.65 0.694,-1.646 0.71,-1.635 0.721,-1.619 0.725,-1.6 0.725,-1.6 0.725,-1.175 0.729,-1.156 0.74,-1.14 0.756,-1.129 0.775,-1.125 0.775,-1.125 1.1,-1.125 1.119,-1.121 1.135,-1.11 1.146,-1.094 1.15,-1.075 1.15,-1.075 1.15,-0.925 1.146,-0.906 1.135,-0.89 1.119,-0.879 1.1,-0.875 1.1,-0.875 0.425,-0.875 0.406,-0.879 0.39,-0.89 0.379,-0.906 0.375,-0.925 0.375,-0.925
  Top Layer region: 0.375,0.925 0.375,1.6 0.379,1.619 0.39,1.635 0.406,1.646 0.425,1.65 0.425,1.65 0.675,1.65 0.694,1.646 0.71,1.635 0.721,1.619 0.725,1.6 0.725,1.6 0.725,1.175 0.729,1.156 0.74,1.14 0.756,1.129 0.775,1.125 0.775,1.125 1.1,1.125 1.119,1.121 1.135,1.11 1.146,1.094 1.15,1.075 1.15,1.075 1.15,0.925 1.146,0.906 1.135,0.89 1.119,0.879 1.1,0.875 1.1,0.875 0.425,0.875 0.406,0.879 0.39,0.89 0.379,0.906 0.375,0.925
  Top Layer region: -1.15,0.925 -1.15,1.075 -1.146,1.094 -1.135,1.11 -1.119,1.121 -1.1,1.125 -1.1,1.125 -0.775,1.125 -0.756,1.129 -0.74,1.14 -0.729,1.156 -0.725,1.175 -0.725,1.175 -0.725,1.6 -0.721,1.619 -0.71,1.635 -0.694,1.646 -0.675,1.65 -0.675,1.65 -0.425,1.65 -0.406,1.646 -0.39,1.635 -0.379,1.619 -0.375,1.6 -0.375,1.6 -0.375,0.925 -0.379,0.906 -0.39,0.89 -0.406,0.879 -0.425,0.875 -0.425,0.875 -1.1,0.875 -1.119,0.879 -1.135,0.89 -1.146,0.906 -1.15,0.925
  body extent -1,-1.5 1,1.5, height 1
Samtec_HTSW-102-07-G-S [mm] "Samtec 100mil, 1x2, 230 mil above insulator"
  rrect6% 1.65x1.65 hole 1.016: 1(-1.27,0)
  round 1.65 hole 1.016: 2(1.27,0)
  silkscreen extent -3.3,-1.27 2.54,1.27, body extent -2.54,-1.27 2.54,1.27, height 8.38
Samtec_HTSW-103-07-G-S [mm] "Samtec 100mil, 1x3, 230 mil above insulator"
  rrect6% 1.65x1.65 hole 1.016: 1(-2.54,0)
  round 1.65 hole 1.016: 2(0,0) 3(2.54,0)
  silkscreen extent -4.57,-1.27 3.81,1.27, body extent -3.81,-1.27 3.81,1.27, height 8.38
SMB [mm] "Molded Diode, 2-Leads, Body 5.4x3.6mm, IPC Medium Density, based on OnSemi component dimensions"
  rect 2.159x2.743 smd: 1(-2.21,0) 2(2.21,0)
  silkscreen extent -3.94,-2.08 3.17,2.08, body extent -2.7,-1.8 2.7,1.8, height 2.32
SOT-23 [mm] "SOT23, 3-Leads, Body 2.9x1.3mm, Pitch 0.95mm, Lead Span 2.5mm, IPC Medium Density"
  rrect50% 1x0.6 smd: 1(-1.2,0.95) 2(-1.2,-0.95) 3(1.2,0)
  silkscreen extent -1.62,-1.5 0.7,1.5, body extent -1.16,-1.45 1.21,1.45, height 1
TO-277A [mm] "Vishay"
  rect 1.4x1.27 smd: 1(-1.04,1.83) 2(1.04,1.83)
  rect 4.72x4.8 smd: 3(0,-1.883)
  body extent -2.35,-4.2 2.4,2.45, height 1.2
VCHA042A [mm] "CYNTEC"
  rrect7% 1.5x3.5 smd: 1(-1.85,0) 2(1.85,0)
  silkscreen extent -2.2,-2.25 2.2,2.25, body extent -2.25,-2.15 2.25,2.15, height 2.11
WURTH_61300211121#1 [mm] "Header, 2.54mm, 2x1, TH"
  rect 1.65x1.65 hole 1.15: 1(-1.27,0)
  round 1.65 hole 1.15: 2(1.27,0)
  silkscreen extent -2.54,-1.27 2.54,1.6, body extent -2.54,-1.27 2.54,1.27, height 8.54
WURTH_61300211121#2 [mm] "Header, 2.54mm, 2x1, TH"
  rrect50% 1.65x1.65 hole 1.15: 1(-1.27,0)
  round 1.65 hole 1.15: 2(1.27,0)
  body extent -2.54,-1.27 2.54,1.27, height 8.54
WURTH_61300311121#1 [mm] "Header, 2.54mm, 3x1, TH"
  rect 1.65x1.65 hole 1.15: 1(-2.54,0)
  round 1.65 hole 1.15: 2(0,0) 3(2.54,0)
  silkscreen extent -3.81,-1.27 3.81,1.6, body extent -3.81,-1.27 3.81,1.27, height 8.54
WURTH_61300311121#2 [mm] "Header, 2.54mm, 3x1, TH"
  rrect50% 1.65x1.65 hole 1.15: 1(-2.54,0)
  round 1.65 hole 1.15: 2(0,0) 3(2.54,0)
  body extent -3.81,-1.27 3.81,1.27, height 8.54

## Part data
C1: library part CMP-0008969-2, "CAP, CERM, 4.7 uF, 50 V, +/- 10%, X7R, 1206", Cap_Case=2220, Manufacturer=MuRata, PartNumber=GRM31CR71H475KA12L, Supplier Part Number 1=24R6347, TempCo=X7R, Tolerance_%=10%, Value1=Unknown, Value2=50V, ValueDisplayed=4.7uF
C2: library part CMP-0006356-2, "CAP, CERM, 0.1 uF, 50 V, +/- 10%, X7R, AEC-Q200 Grade 1, 0402", Cap_Case=0402, Manufacturer=MuRata, PartNumber=GCM155R71H104KE02D, Supplier Part Number 1=490-10672-1-ND, TempCo=X7R, Tolerance_%=10%, Value1=Unknown, Value2=50V, ValueDisplayed=0.1uF
C3: library part CMP-0006295-2, "CAP, CERM, 0.1 uF, 25 V, +/- 20%, X7R, 0402", Cap_Case=0402, Manufacturer=TDK, PartNumber=C1005X7R1E104M050BB, Supplier Part Number 1=445-7349-1-ND, TempCo=X7R, Tolerance_%=20%, Value1=Unknown, Value2=25V, ValueDisplayed=0.1uF
C4 C5: library part CMP-0092611-1, "Chip Multilayer Ceramic Capacitors for General Purpose, 1206, 22uF, X6S, 22%, 10%, 25V", Manufacturer=Murata, Operating Temperature Range="-55°C to +105°C", Part Number=GRM31CC81E226KE11L, TempCo=22%, Temperature Characteristic=X6S, Tolerance_%=10%, ValueDisplayed=22uF
C6: library part CMP-0085950-1, "CAP, CERM, 10 µF, 50 V,+/- 10%, X7R, AEC-Q200 Grade 1, 1206", Cap_Case=1206, Manufacturer=TDK, PartNumber=CGA5L1X7R1H106K160AC, TempCo=X7R, Tolerance_%=10%, Value2=50V, ValueDisplayed=10µF
C7 C10 C43: library part CMP-0006317-2, "CAP, CERM, 2200 pF, 50 V, +/- 10%, X7R, AEC-Q200 Grade 1, 0402", Cap_Case=0402, Manufacturer=TDK, Supplier Part Number 1=445-5606-1-ND, TempCo=X7R, Tolerance_%=10%, Value1="1.07794 ohm", Value2=50V, ValueDisplayed=2200pF
C8: library part CMP-0006831-4, "CAP, CERM, 1 uF, 16 V, +/- 10%, X7R, 0603", Cap_Case=0603, Manufacturer="Wurth Elektronik", PartNumber=885012206052, Supplier Part Number 1=710-885012206052, TempCo=X7R, Tolerance_%=10%, Value1=Unknown, Value2=16V, ValueDisplayed=1uF
C9 C14 C15 C24 C25: library part CMP-0008811-2, "CAP, CERM, 22 uF, 10 V, +/- 10%, X7R, AEC-Q200 Grade 1, 1206", Cap_Case=1206, Manufacturer=MuRata, TempCo=X7R, Tolerance_%=10%, Value1=Unknown, Value2=10V, ValueDisplayed=22uF
C11: library part CMP-0007133-4, "CAP, CERM, 2.2 uF, 10 V, +/- 10%, X7S, 0603", Alternate Manufacturer=TDK, Alternate PartNumber=CGA3E3X7S1A225K080AB, Cap_Case=0603, Manufacturer=MuRata, TempCo=X7S, Tolerance_%=10%, Value1=Unknown, Value2=10V, ValueDisplayed=2.2uF
C12: library part CMP-0006360-2, "CAP, CERM, 470 pF, 50 V, +/- 10%, X7R, AEC-Q200 Grade 1, 0402", Cap_Case=0402, Manufacturer=MuRata, Supplier Part Number 1=490-4913-1-ND, TempCo=X7R, Tolerance_%=10%, Value1=Unknown, Value2=50V, ValueDisplayed=470pF
C13: library part CMP-0006348-2, "CAP, CERM, 22 pF, 50 V, +/- 5%, C0G/NP0, AEC-Q200 Grade 1, 0402", Cap_Case=0402, Manufacturer=MuRata, Supplier Part Number 1=490-9648-1-ND, TempCo=C0G/NP0, Tolerance_%=5%, Value1=Unknown, Value2=50V, ValueDisplayed=22pF
C16 C17 C18: library part CMP-0009204-2, "CAP, CERM, 100 uF, 6.3 V, +/- 20%, X5R, 1210", Cap_Case=1210, Manufacturer=MuRata, Supplier Part Number 1=490-3390-1-ND, TempCo=X5R, Tolerance_%=20%, Value1="0.002 ohm", Value2=6.3V, ValueDisplayed=100uF
C19: library part CMP-0006361-2, "CAP, CERM, 4700 pF, 50 V, +/- 10%, X7R, AEC-Q200 Grade 1, 0402", Cap_Case=0402, Manufacturer=MuRata, Supplier Part Number 1=490-4915-1-ND, TempCo=X7R, Tolerance_%=10%, Value1=Unknown, Value2=50V, ValueDisplayed=4700pF
C20: library part CMP-0860290-1, "CAP, CERM, 10 pF, 50 V,+/- 5%, C0G/NP0, AEC-Q200 Grade 1, 0402", Cap_Case=0402, Manufacturer=MuRata, TempCo=C0G/NP0, Tolerance_%=5%, Value2=50V, ValueDisplayed=10pF
C21 C33: library part CMP-0006237-2, "CAP, CERM, 0.1 uF, 16 V, +/- 10%, X7R, AEC-Q200 Grade 1, 0402", Cap_Case=0402, Manufacturer=Kemet, Supplier Part Number 1=399-6828-1-ND, TempCo=X7R, Tolerance_%=10%, Value1=Unknown, Value2=16V, ValueDisplayed=0.1uF
C22 C23 C26 C27: library part CMP-0007497-5, "CAP, CERM, 10 uF, 10 V, +/- 20%, X7R, 0603", Cap_Case=0603, Manufacturer=MuRata, Supplier Part Number 1=81-GRM188Z71A106MA3D, TempCo=X7R, Tolerance_%=20%, Value1=Unknown, Value2=10V, ValueDisplayed=10uF
C28: library part CMP-0007398-4, "CAP, CERM, 0.47 uF, 16 V, +/- 10%, X7R, 0603", Cap_Case=0603, Manufacturer=MuRata, Supplier Part Number 1=490-3295-1-ND, TempCo=X7R, Tolerance_%=10%, Value1=Unknown, Value2=16V, ValueDisplayed=0.47uF
C29: library part CMP-0006320-2, "CAP, CERM, 470 pF, 50 V, +/- 10%, X7R, AEC-Q200 Grade 1, 0402", Cap_Case=0402, Manufacturer=TDK, Supplier Part Number 1=445-6888-1-ND, TempCo=X7R, Tolerance_%=10%, Value1="4.96489 ohm", Value2=50V, ValueDisplayed=470pF
C30 C35 C36 C41 C42 C45: "CAP, CERM, 0.1 µF, 50 V, +/- 10%, X7R, 0603", Cap_Case=0603, Manufacturer=MuRata, Supplier Part Number 1=490-1519-1-ND, TempCo=X7R, Tolerance_%=10, Value1=Unknown, Value2=50V, ValueDisplayed=0.1µF
C31: "CAP, CERM, 270 pF, 50 V,+/- 10%, X7R, 0603", Cap_Case=0603, Manufacturer=MuRata, Supplier Part Number 1=490-1485-1-ND, TempCo=X7R, Tolerance_%=10, Value2=50V, ValueDisplayed=270pF
C32: "CAP, CERM, 0.01 µF, 100 V, +/- 10%, X7R, 0603", Cap_Case=0603, Manufacturer=MuRata, Supplier Part Number 1=GRM188R72A103KA01D-ND, TempCo=X7R, Tolerance_%=10, Value1=Unknown, Value2=100V, ValueDisplayed=0.01µF
C34 C37 C38 C39: "CAP, CERM, 10 µF, 50 V, +/- 10%, X7R, 1210", Cap_Case=1210, Manufacturer=MuRata, Supplier Part Number 1=490-6544-1-ND, TempCo=X7R, Tolerance_%=10, Value1=Unknown, Value2=50V, ValueDisplayed=10µF
C40: "CAP, CERM, 10 µF, 50 V, +/- 10%, X7R, 1210", Cap_Case=1210, Manufacturer=MuRata, Supplier Part Number 1=490-6544-1-ND, TempCo=X7R, Tolerance_%=10, Value1=Unknown, Value2=50V, ValueDisplayed=open
C44: "CAP, CERM, 2.2 µF, 50 V, +/- 10%, X7R, 1206", Cap_Case=1206, Manufacturer=MuRata, Supplier Part Number 1=490-3367-1-ND, TempCo=X7R, Tolerance_%=10, Value1=Unknown, Value2=50V, ValueDisplayed=2.2µF
C46: "CAP, CERM, 4.7 µF, 16 V, +/- 10%, X7R, 0805", Cap_Case=0805, Manufacturer=MuRata, Supplier Part Number 1=490-4522-1-ND, TempCo=X7R, Tolerance_%=10, Value1="0.006 ohm", Value2=16V, ValueDisplayed=4.7µF
C47: "CAP, CERM, 0.47 µF, 25 V,+/- 10%, X7R, 0603", Cap_Case=0603, Manufacturer=MuRata, Supplier Part Number 1=490-3291-1-ND, TempCo=X7R, Tolerance_%=10, Value2=25V, ValueDisplayed=0.47µF
C48: "CAP, CERM, 0.068 µF, 50 V,+/- 10%, X7R, 0603", Cap_Case=0603, Manufacturer=MuRata, Supplier Part Number 1=490-3288-1-ND, TempCo=X7R, Tolerance_%=10, Value2=50V, ValueDisplayed=0.068µF
D1: "Diode, Zener, 16 V, 225 mW, SOT-23", Manufacturer="ON Semiconductor", Power_W=0.225, Supplier Part Number 1=BZX84C16LT1GOSCT-ND, Value1=0.225W
D2: library part SMBJ33CA-13-F, "Diode, TVS, Bi, 36 V, SMB", Manufacturer=Vishay-Semiconductor, Power_W=5, Value1=5W
D3: library part BAV99-7-F, "Diode, Switching, 75 V, 0.3 A, SOT-23", Manufacturer="Diodes Inc.", Supplier Part Number 1=BAV99-FDICT-ND, Value1=0.3A, Value2=1.25V
D4: library part SS5P6-M3/86A, "Diode, Schottky, 60 V, 5 A, TO-277A", Manufacturer=Vishay-Semiconductor, Supplier Part Number 1=SS5P6-M3/86AGICT-ND, Value1=5A, Value2=0.69V
J1 J5 J6 J7 J8: library part CMP-0074959-1, "Terminal Block, 2x1, 5.08mm, TH", Manufacturer="On-Shore Technology", Supplier Part Number 1=ED2580-ND
J2 J3 J11 J12 J14 J15 J16: library part CMP-0075483-1, "Header, 100mil, 2x1, Gold, TH", Manufacturer=Samtec, PartNumber=HTSW-102-07-G-S, Supplier Part Number 1=SAM8736-ND
J4 J13: library part CMP-0075484-1, "Header, 100mil, 3x1, Gold, TH", Manufacturer=Samtec, PartNumber=HTSW-103-07-G-S, Supplier Part Number 1=HTSW-103-07-G-S-ND
J9: "Header, 2.54 mm, 3x1, Gold, TH", Manufacturer="Wurth Elektronik", Supplier Part Number 1=732-5316-ND
J10: "Header, 2.54 mm, 2x1, Gold, TH", Manufacturer="Wurth Elektronik", Supplier Part Number 1=732-5315-ND
JP1 JP3 JP4: library part CMP-0054796-2, "Header, 2.54 mm, 3x1, Gold, TH", Color=Black, Manufacturer="Wurth Elektronik", Supplier Part Number 1=732-5316-ND
JP2 JP5: library part CMP-0054794-2, "Header, 2.54 mm, 2x1, Gold, TH", Color=Black, Manufacturer="Wurth Elektronik", Supplier Part Number 1=732-5315-ND
L1: library part CMP-0091207-1, "Molded Power Inductor, Shielded, 2.2uH 20%, 7.2A, 23mOhm DCR Max, AEC-Q200, T/R", Manufacturer=Coilcraft, Operating Temperature Range="to +165°C", Self Resonant Frequency=52MHz, Test Frequency=1MHz, Tolerance_%=20%
L2: library part CMP-0092762-2, "Power Inductor, shielded, composite, 20% tol, SMT, RoHS, halogen-free   USD 0.580", Manufacturer=Coilcraft, Operating Temperature Range="to +165°C", Part Number=XGL3530-332MEC, Self Resonant Frequency=43MHz, Test Frequency=1MHz, Tolerance_%=20%
L3: library part CMP-0058944-1, "Inductor, Shielded, 470 nH, 4.7 A, 0.021 ohm, SMD", Manufacturer="MuRata Toko", Value1="0.021 ohm", Value2=4.7A, ValueDisplayed=470nH
L4 L5: library part VCHA042A-1R0MS6, "Inductor, 3.3 µH, 8.8 A, 0.028 ohm, AEC-Q200 Grade 0, SMD", Manufacturer=Cyntec, Value1="0.028 ohm", ValueDisplayed=3.3uH
Q1: library part SQJ469EP-T1-GE3, "MOSFET, P-CH, -60 V, -52 A, AEC-Q101, PowerPAK_SO-8L", Alternate Manufacturer=None, Manufacturer=Vishay-Siliconix, PartNumber=SQJ459EP-T1_GE3, Value1="? ohm", Value2="73 nC"
Q2 Q4 Q5: library part CMP-0092475-1, "Trans Digital BJT NPN/PNP 50V 100mA 300mW Automotive 6-Pin TSSOP T/R", Collector Base Voltage=50V, Digikey Part Number=1727-4329-1-ND, Emitter Base Voltage=5V, Manufacturer=Nexperia, Mouser Part Number=771-PUMD13-T/R, Operating Temperature Range="to +150°C", Power_W=300mW, Unity Gain Freq=230/180MHz
Q3: library part SQJA60EP, "MOSFET, N-CH, 60 V, 23 A, AEC-Q101, PowerPAK_SO-8L", Alternate Manufacturer=None, Manufacturer=Vishay-Siliconix, PartNumber=SQJ158EP, Value1="0.03 ohm", Value2="17 nC"
R1 R33: library part CMP-0025950-3, "RES, 100 k, 1%, 0.063 W, AEC-Q200 Grade 0, 0402", Manufacturer=Vishay-Dale, PartNumber=CRCW0402100KFKED, Power_W=63mW, Supplier Part Number 1=541-100KLCT-ND, TempCo="100 ppm/C", Tolerance_%=1%, Value2=0.063W, Value_Code=100k
R2 R5 R7 R29 R34: library part CMP-0026822-3, "RES, 0, 5%, 0.063 W, AEC-Q200 Grade 0, 0402", Manufacturer=Vishay-Dale, PartNumber=CRCW04020000Z0ED, Power_W=63mW, Supplier Part Number 1=541-0.0JCT-ND, TempCo="200 ppm/C", Tolerance_%=5%, Value2=0.063W, Value_Code=0000, ValueDisplayed=0
R3: library part CMP-0026515-2, "RES, 6.49 k, 1%, 0.063 W, AEC-Q200 Grade 0, 0402", Manufacturer=Vishay-Dale, PartNumber=CRCW04026K49FKED, Power_W=63mW, Supplier Part Number 1=541-6.49KLCT-ND, TempCo="100 ppm/C", Tolerance_%=1%, Value2=0.063W, Value_Code=6k49, ValueDisplayed=6.49k
R4: library part CMP-0025697-4, "RES, 0, 5%, 0.1 W, AEC-Q200 Grade 0, 0603", Manufacturer=Vishay-Dale, PartNumber=CRCW06030000Z0EA, Power_W=100mW, Supplier Part Number 1=541-0.0GCT-ND, TempCo="200 ppm/C", Tolerance_%=5%, Value2=0.1W, Value_Code=0000, ValueDisplayed=0
R6: library part CMP-0026162-2, "RES, 20.0 k, 1%, 0.063 W, AEC-Q200 Grade 0, 0402", Manufacturer=Vishay-Dale, Power_W=63mW, Supplier Part Number 1=541-20.0KLCT-ND, TempCo="100 ppm/C", Tolerance_%=1%, Value2=0.063W, Value_Code=20k0, ValueDisplayed=20.0k
R8: library part CMP-0026294-2, "RES, 32.4 k, 1%, 0.063 W, AEC-Q200 Grade 0, 0402", Manufacturer=Vishay-Dale, Power_W=63mW, Supplier Part Number 1=541-32.4KLCT-ND, TempCo="100 ppm/C", Tolerance_%=1%, Value2=0.063W, Value_Code=32k4, ValueDisplayed=32.4k
R9 R12: library part CMP-0026588-2, "RES, 8.06 k, 1%, 0.063 W, AEC-Q200 Grade 0, 0402", Manufacturer=Vishay-Dale, Power_W=63mW, Supplier Part Number 1=541-8.06KLCT-ND, TempCo="100 ppm/C", Tolerance_%=1%, Value2=0.063W, Value_Code=8k06, ValueDisplayed=8.06k
R10: library part CMP-0026570-2, "RES, 80.6 k, 1%, 0.063 W, AEC-Q200 Grade 0, 0402", Manufacturer=Vishay-Dale, Power_W=63mW, Supplier Part Number 1=541-80.6KLCT-ND, TempCo="100 ppm/C", Tolerance_%=1%, Value2=0.063W, Value_Code=80k6, ValueDisplayed=88.7k
R11: library part CMP-0026367-2, "RES, 40.2 k, 1%, 0.063 W, AEC-Q200 Grade 0, 0402", Manufacturer=Vishay-Dale, Power_W=63mW, Supplier Part Number 1=541-40.2KLCT-ND, TempCo="100 ppm/C", Tolerance_%=1%, Value2=0.063W, Value_Code=40k2, ValueDisplayed=19.6k
R13: "RES, 10.0, 1%, 0.1 W, 0603", Manufacturer=Vishay-Dale, Power_W=0.1, Supplier Part Number 1=541-10.0HCT-ND, TempCo="100 ppm/C", Tolerance_%=1, Value1=1%, Value2=0.1W, Value_Code=10R0, ValueDisplayed=10.0
R14: "RES, 8.2, 5%, 0.25 W, 1206", Manufacturer=Vishay-Dale, Power_W=0.25, Supplier Part Number 1=541-8.2ECT-ND, TempCo="200 ppm/C", Tolerance_%=5, Value1=5%, Value2=0.25W, Value_Code=8R20, ValueDisplayed=8.2
R15: "RES, 3.32, 1%, 0.1 W, 0603", Manufacturer=Vishay-Dale, Power_W=0.1, Supplier Part Number 1=541-3.32HHCT-ND, TempCo="100 ppm/C", Tolerance_%=1, Value1=1%, Value2=0.1W, Value_Code=3R32, ValueDisplayed=3.32
R16: "RES, 49.9 k, 1%, 0.1 W, 0603", Manufacturer=Vishay-Dale, Power_W=0.1, Supplier Part Number 1=541-49.9KHCT-ND, TempCo="100 ppm/C", Tolerance_%=1, Value1=1%, Value2=0.1W, Value_Code=49k9, ValueDisplayed=49.9k
R17: "RES, 4.75, 1%, 0.1 W, 0603", Manufacturer=Vishay-Dale, Power_W=0.1, Supplier Part Number 1=541-4.75HHCT-ND, TempCo="100 ppm/C", Tolerance_%=1, Value1=1%, Value2=0.1W, Value_Code=4R75, ValueDisplayed=4.75
R18: library part CMP-0026763-1, "RES, 100, 1%, 0.063 W, AEC-Q200 Grade 0, 0402", Manufacturer="Stackpole Electronics Inc", Power_W=63mW, Supplier Part Number 1=RMCF0402JT100RCT-ND, TempCo="100 ppm/C", Tolerance_%=1%, Value2=0.063W, Value_Code=100R, ValueDisplayed=100
R19: "RES, 0.008, 1%, 1 W, 0612", Manufacturer="Susumu Co Ltd", Power_W=1, Supplier Part Number 1=PRL1632.008FCT-ND, TempCo="350 ppm/C", Value1=1%, Value2=1W, Value_Code=8L000, ValueDisplayed=0.008
R20 R21 R22: library part CMP-0026992-3, "RES, 0, 5%, 0.1 W, AEC-Q200 Grade 0, 0402", Manufacturer=Panasonic, Power_W=100mW, Supplier Part Number 1=P0.0JCT-ND, TempCo="600 ppm/C", Tolerance_%=5%, Value2=0.1W, Value_Code=0000, ValueDisplayed=0
R23: library part CMP-0026445-2, "RES, 53.6 k, 1%, 0.063 W, AEC-Q200 Grade 0, 0402", Manufacturer=Vishay-Dale, Power_W=63mW, Supplier Part Number 1=541-53.6KLCT-ND, TempCo="100 ppm/C", Tolerance_%=1%, Value2=0.063W, Value_Code=53k6, ValueDisplayed=53.6k
R24: library part CMP-0026621-3, "RES, 9.53 k, 1%, 0.063 W, AEC-Q200 Grade 0, 0402", Manufacturer=Vishay-Dale, Power_W=63mW, Supplier Part Number 1=541-9.53KLCT-ND, TempCo="100 ppm/C", Tolerance_%=1%, Value2=0.063W, Value_Code=9k53, ValueDisplayed=9.53k
R25: library part CMP-0026827-3, "RES, 10, 5%, 0.063 W, AEC-Q200 Grade 0, 0402", Manufacturer=Vishay-Dale, Power_W=63mW, Supplier Part Number 1=541-10JCT-ND, TempCo="200 ppm/C", Tolerance_%=5%, Value2=0.063W, Value_Code=10R0, ValueDisplayed=10
R26: library part CMP-0026159-2, "RES, 200, 1%, 0.063 W, AEC-Q200 Grade 0, 0402", Manufacturer=Vishay-Dale, Power_W=63mW, Supplier Part Number 1=541-200LCT-ND, TempCo="100 ppm/C", Tolerance_%=1%, Value2=0.063W, Value_Code=200R, ValueDisplayed=200
R27 R28 R31 R32: library part CMP-0077731-1, "RES, 10.0 k, 1%, 0.063 W, AEC-Q200 Grade 0, 0402", Manufacturer="Yageo America", Power_W=63mW, Supplier Part Number 1=YAG3436CT-ND, TempCo="100 ppm/C", Tolerance_%=1%, Value2=0.063W, Value_Code=10k0, ValueDisplayed=10.0k
R30: library part CMP-0026936-3, "RES, 47, 5%, 0.063 W, AEC-Q200 Grade 0, 0402", Manufacturer=Vishay-Dale, Power_W=63mW, Supplier Part Number 1=541-47JCT-ND, TempCo="200 ppm/C", Tolerance_%=5%, Value2=0.063W, Value_Code=47R0, ValueDisplayed=47
TP1 TP4 TP6: library part CMP-0055137-1, "Test Point, Miniature, Red, TH", Color=Red, Manufacturer=Keystone, Supplier Part Number 1=36-5000-ND
TP2 TP5 TP7: library part CMP-0055138-2, "Test Point, Miniature, Black, TH", Color=Black, Manufacturer="Keystone Electronics", Supplier Part Number 1=36-5001-ND
TP8 TP10: "Test Point, Miniature, Red, TH", Color=Red, Manufacturer=Keystone, Supplier Part Number 1=36-5000-ND
TP9 TP11: "Test Point, Miniature, Black, TH", Color=Black, Manufacturer=Keystone, Supplier Part Number 1=36-5001-ND
U1: library part CMP-0091397-1, "36-V, 2-A Buck Converter with 1.5 µA IQ in 2-mm x 2-mm HotRod QFN", Manufacturer="Texas Instruments", Max Supply Voltage=36V, Min Supply Voltage=3V, Nominal Supply Current=0.13uA, Operating Temperature Range="-40°C to +150°C", Output Voltage=1-34.2V, Part Number=LMR43620MSC3RPERQ1, Switching Frequency=2.2MHz
U2: library part CMP-0082642-1, "Automotive Low Input Voltage, Adjustable-Frequency Step-down Converter, RWY0009A (VQFN-HR-9)", Alternate Manufacturer="Texas Instruments", Operating Temperature Range="-40 to 150 C", Rating=Automotive
U3: library part CMP-0860101-1, "2.7-V to 6-V Adjustable-Frequency Step-Down Converter, DRL0008A (SOT-5X3-8)", Alternate Manufacturer="Texas Instruments"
